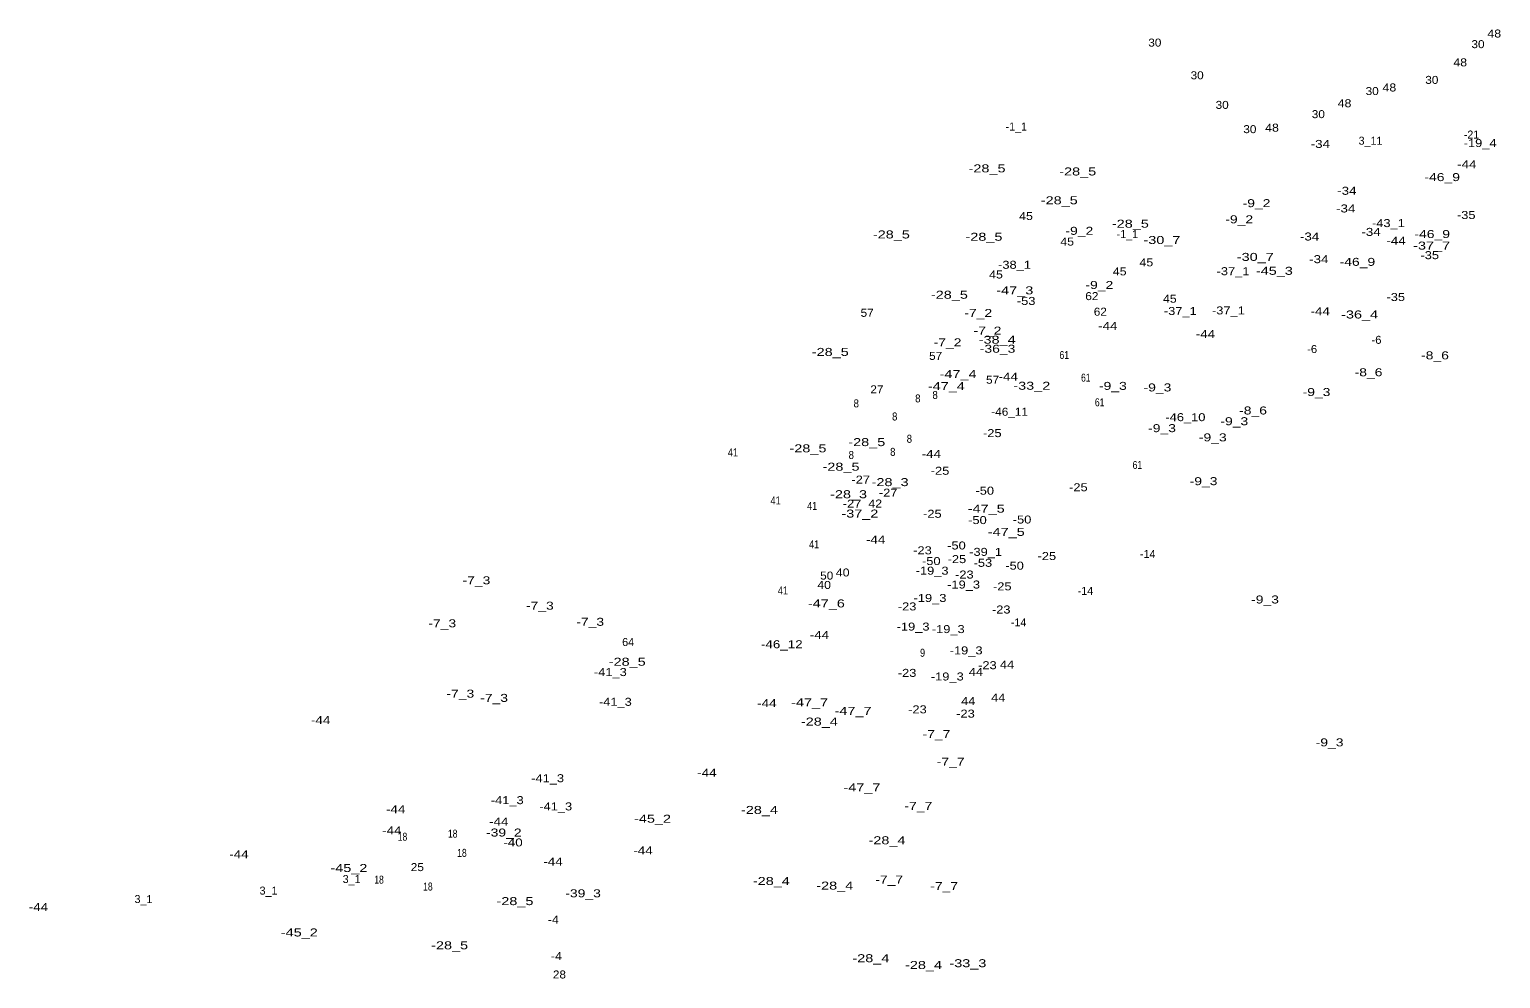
# Model space of a CAD drawing. Extents: x -663241 to -661169, y -1003538 to -1000899.
# Drawn here: x -662800 to -662065, y -1002217 to -1001743 of the extents above; entities that cross this region are included whole.
import ezdxf
from ezdxf.enums import TextEntityAlignment as Align

# ---------------------------------------------------------------- set-up
doc = ezdxf.new("R2010")
doc.units = 0
doc.header["$LTSCALE"] = 1.6
doc.layers.add('24', color=7, linetype='Continuous')

msp = doc.modelspace()

# ---------------------------------------------------------------- texts
at = {"layer": '24'}
for s, width, p in [('48', 1.15, (-662068.16, -1001746.79)), ('30', 1.1, (-662237.77, -1001751.33)), ('30', 1.1, (-662076.29, -1001752.1)), ('48', 1.15, (-662085.169, -1001761.22)), ('30', 1.1, (-662216.63, -1001767.67)), ('30', 1.1, (-662099.36, -1001769.98)), ('30', 1.1, (-662129.16, -1001775.56)), ('48', 1.15, (-662120.569, -1001773.77)), ('30', 1.1, (-662204.13, -1001782.48)), ('48', 1.15, (-662142.97, -1001781.65)), ('48', 1.15, (-662179.209, -1001793.86)), ('30', 1.1, (-662156.069, -1001787.1)), ('30', 1.1, (-662190.29, -1001794.6)), ('-34', 1.25, (-662155.06, -1001801.99)), ('-19_4', 1.2, (-662075.23, -1001801.55)), ('-28_5', 1.35, (-662321.61, -1001814.22)), ('-28_5', 1.35, (-662276.299, -1001815.76)), ('-44', 1.25, (-662081.86, -1001812.15)), ('-46_9', 1.3, (-662094.191, -1001818.58)), ('-28_5', 1.35, (-662285.52, -1001830.17)), ('-34', 1.25, (-662141.82, -1001825.42)), ('45', 1.15, (-662302.14, -1001838.04)), ('-9_2', 1.3, (-662186.97, -1001831.61)), ('-34', 1.25, (-662142.39, -1001834.26)), ('-35', 1.2, (-662082.16, -1001837.53)), ('-9_2', 1.3, (-662275.49, -1001845.44)), ('-28_5', 1.35, (-662250, -1001841.88)), ('-9_2', 1.3, (-662195.61, -1001839.68)), ('-43_1', 1.2, (-662121.059, -1001841.57)), ('-28_5', 1.35, (-662369.419, -1001847.25)), ('-28_5', 1.35, (-662323.15, -1001848.41)), ('45', 1.15, (-662281.569, -1001850.83)), ('-30_7', 1.35, (-662234.23, -1001850.03)), ('-34', 1.25, (-662160.44, -1001848.28)), ('-34', 1.25, (-662129.72, -1001845.97)), ('-44', 1.25, (-662117.23, -1001850.42)), ('-37_7', 1.35, (-662099.471, -1001852.83)), ('-46_9', 1.3, (-662099.181, -1001847.05)), ('-30_7', 1.35, (-662187.57, -1001858.48)), ('-34', 1.25, (-662155.83, -1001859.61)), ('-35', 1.2, (-662100.4, -1001857.61)), ('45', 1.15, (-662317.13, -1001867.27)), ('-38_1', 1.2, (-662307.88, -1001862.42)), ('45', 1.15, (-662255.329, -1001865.73)), ('45', 1.15, (-662242.01, -1001861.21)), ('-37_1', 1.2, (-662198.7, -1001865.62)), ('-45_3', 1.35, (-662178.05, -1001865.44)), ('-46_9', 1.3, (-662136.551, -1001860.96)), ('-9_2', 1.3, (-662265.5, -1001872.52)), ('-28_5', 1.35, (-662340.429, -1001877.4)), ('-47_3', 1.35, (-662307.74, -1001875.21)), ('-53', 1.2, (-662302.07, -1001880.5)), ('62', 1.1, (-662269.24, -1001878.09)), ('45', 1.15, (-662230.28, -1001879.38)), ('-35', 1.2, (-662117.39, -1001878.54)), ('57', 1.1, (-662381.52, -1001886.43)), ('-7_2', 1.3, (-662326.01, -1001886.5)), ('62', 1.1, (-662265.01, -1001885.88)), ('-37_1', 1.2, (-662225.04, -1001885.52)), ('-37_1', 1.2, (-662201.01, -1001885.23)), ('-44', 1.25, (-662155.1, -1001885.62)), ('-36_4', 1.35, (-662135.45, -1001887.27)), ('-7_2', 1.3, (-662321.4, -1001895.34)), ('-44', 1.25, (-662261.29, -1001893)), ('-7_2', 1.3, (-662341.37, -1001901.2)), ('-38_4', 1.35, (-662316.55, -1001899.89)), ('-44', 1.25, (-662212.47, -1001897.04)), ('-6', 1.05, (-662127.02, -1001899.94)), ('-28_5', 1.35, (-662399.949, -1001905.99)), ('57', 1.1, (-662347.3, -1001907.97)), ('-36_3', 1.3, (-662316.35, -1001904.4)), ('61', 0.8, (-662283.03, -1001907.52)), ('-6', 1.05, (-662159.18, -1001904.55)), ('-8_6', 1.3, (-662097.78, -1001907.71)), ('-47_4', 1.35, (-662336.09, -1001917.05)), ('-44', 1.25, (-662311.01, -1001918.34)), ('61', 0.8, (-662272.26, -1001918.86)), ('-8_6', 1.3, (-662131, -1001916.16)), ('27', 1.1, (-662376.65, -1001924.7)), ('-47_4', 1.35, (-662341.949, -1001923.11)), ('57', 1.1, (-662318.85, -1001919.9)), ('-33_2', 1.35, (-662299.25, -1001922.91)), ('-9_3', 1.3, (-662258.75, -1001922.97)), ('-9_3', 1.3, (-662236.47, -1001923.74)), ('-9_3', 1.3, (-662156.98, -1001926.05)), ('8', 0.9, (-662386.959, -1001931.73)), ('8', 0.9, (-662356.199, -1001929.23)), ('8', 0.9, (-662347.559, -1001927.51)), ('61', 0.8, (-662265.341, -1001931.17)), ('8', 0.9, (-662367.74, -1001938.27)), ('-46_11', 1.1, (-662310.33, -1001935.89)), ('-46_10', 1.2, (-662222.49, -1001938.62)), ('-9_3', 1.3, (-662198.07, -1001940.64)), ('-8_6', 1.3, (-662188.7, -1001935.27)), ('-25', 1.2, (-662318.99, -1001946.58)), ('-9_3', 1.3, (-662234.17, -1001944.1)), ('-28_5', 1.35, (-662411.09, -1001954.2)), ('-28_5', 1.35, (-662381.709, -1001951.09)), ('8', 0.9, (-662360.429, -1001949.42)), ('-9_3', 1.3, (-662208.82, -1001948.71)), ('41', 0.85, (-662448.6, -1001956.23)), ('8', 0.9, (-662389.459, -1001957.5)), ('8', 0.9, (-662368.699, -1001955.96)), ('-44', 1.25, (-662349.449, -1001956.99)), ('61', 0.8, (-662246.5, -1001962.52)), ('-28_5', 1.35, (-662394.579, -1001963.38)), ('-27', 1.2, (-662384.75, -1001969.84)), ('-25', 1.2, (-662345.1, -1001965.41)), ('-28_3', 1.35, (-662390.799, -1001977.14)), ('-28_3', 1.35, (-662370.059, -1001971.09)), ('-27', 1.2, (-662371.02, -1001976.37)), ('-50', 1.2, (-662322.76, -1001975.36)), ('-25', 1.2, (-662275.98, -1001973.66)), ('-9_3', 1.3, (-662213.43, -1001970.61)), ('41', 0.85, (-662427.26, -1001980.27)), ('41', 0.85, (-662409, -1001982.96)), ('-27', 1.2, (-662389.071, -1001981.84)), ('42', 1.15, (-662377.47, -1001981.8)), ('-47_5', 1.35, (-662322.02, -1001984.35)), ('-37_2', 1.35, (-662385.16, -1001986.81)), ('-25', 1.2, (-662348.94, -1001986.92)), ('-50', 1.2, (-662326.41, -1001990.07)), ('-50', 1.2, (-662304.11, -1001989.79)), ('-44', 1.25, (-662377.27, -1001999.78)), ('-47_5', 1.35, (-662312.02, -1001995.98)), ('41', 0.85, (-662408.03, -1002002.19)), ('-23', 1.2, (-662353.88, -1002005.2)), ('-50', 1.2, (-662336.89, -1002002.77)), ('-39_1', 1.2, (-662322.321, -1002005.96)), ('-50', 1.2, (-662349.48, -1002010.56)), ('-25', 1.2, (-662336.66, -1002009.58)), ('-53', 1.2, (-662323.69, -1002011.44)), ('-50', 1.2, (-662307.86, -1002012.86)), ('-25', 1.2, (-662291.73, -1002008.05)), ('-7_3', 1.3, (-662576.76, -1002020.18)), ('50', 1.1, (-662401.72, -1002017.82)), ('40', 1.15, (-662393.74, -1002016.26)), ('-19_3', 1.2, (-662349.071, -1002015.37)), ('-23', 1.2, (-662332.95, -1002017.3)), ('41', 0.85, (-662423.61, -1002025.27)), ('40', 1.15, (-662403.02, -1002022.5)), ('-19_3', 1.2, (-662350.12, -1002029.01)), ('-19_3', 1.2, (-662333.321, -1002022.29)), ('-25', 1.2, (-662314, -1002023.22)), ('-7_3', 1.3, (-662545.08, -1002032.87)), ('-47_6', 1.35, (-662401.91, -1002031.74)), ('-23', 1.2, (-662361.56, -1002033.24)), ('-23', 1.2, (-662314.52, -1002034.78)), ('-9_3', 1.3, (-662182.71, -1002029.77)), ('-7_3', 1.3, (-662593.85, -1002041.7)), ('-7_3', 1.3, (-662519.93, -1002040.94)), ('-19_3', 1.2, (-662358.571, -1002043.32)), ('-44', 1.25, (-662405.34, -1002047.48)), ('-19_3', 1.2, (-662341, -1002044.57)), ('-46_12', 1.25, (-662424.17, -1002052.15)), ('9', 0.85, (-662353.84, -1002056.41)), ('-19_3', 1.2, (-662332.071, -1002055.23)), ('-28_5', 1.35, (-662501.41, -1002060.9)), ('44', 1.2, (-662327.16, -1002065.95)), ('-23', 1.2, (-662321.43, -1002062.63)), ('44', 1.2, (-662311.59, -1002062.29)), ('-41_3', 1.2, (-662509.84, -1002066.06)), ('-23', 1.2, (-662361.56, -1002066.47)), ('-19_3', 1.2, (-662341.481, -1002068.27)), ('-7_3', 1.3, (-662584.82, -1002076.85)), ('-7_3', 1.3, (-662567.93, -1002078.97)), ('44', 1.2, (-662331.01, -1002080.56)), ('44', 1.2, (-662316.01, -1002078.83)), ('-41_3', 1.2, (-662507.34, -1002080.93)), ('-44', 1.25, (-662431.62, -1002081.6)), ('-47_7', 1.35, (-662410.27, -1002081.23)), ('-47_7', 1.35, (-662388.551, -1002085.46)), ('-23', 1.2, (-662356.39, -1002084.72)), ('-23', 1.2, (-662332.38, -1002086.83)), ('-44', 1.25, (-662654.61, -1002090.09)), ('-28_4', 1.35, (-662405.39, -1002090.81)), ('-7_7', 1.3, (-662346.9, -1002097.09)), ('-9_3', 1.3, (-662150.45, -1002101.22)), ('-44', 1.25, (-662461.6, -1002116.41)), ('-7_7', 1.3, (-662339.801, -1002110.92)), ('-41_3', 1.2, (-662541.179, -1002119.13)), ('-47_7', 1.35, (-662384.13, -1002123.73)), ('-41_3', 1.2, (-662561.36, -1002130.1)), ('-44', 1.25, (-662617.12, -1002134.67)), ('-41_3', 1.2, (-662537.14, -1002133.24)), ('-45_2', 1.35, (-662488.77, -1002139.39)), ('-28_4', 1.35, (-662435.34, -1002134.99)), ('-7_7', 1.3, (-662355.931, -1002133.01)), ('-44', 1.25, (-662619.04, -1002145.25)), ('18', 0.8, (-662588.62, -1002146.85)), ('-39_2', 1.3, (-662563.08, -1002146.3)), ('-44', 1.25, (-662565.6, -1002140.83)), ('18', 0.8, (-662613.699, -1002148.38)), ('-40', 1.25, (-662558.48, -1002151.24)), ('-28_4', 1.35, (-662371.6, -1002150.16)), ('-44', 1.25, (-662695.439, -1002157.18)), ('18', 0.8, (-662584, -1002156.46)), ('-44', 1.25, (-662538.5, -1002160.83)), ('-44', 1.25, (-662493.52, -1002155.26)), ('-45_2', 1.35, (-662640.48, -1002164.04)), ('25', 1.1, (-662606.299, -1002163.58)), ('18', 0.8, (-662625.429, -1002169.83)), ('18', 0.8, (-662601.01, -1002173.29)), ('-28_4', 1.35, (-662429.39, -1002170.52)), ('-28_4', 1.35, (-662397.71, -1002172.83)), ('-7_7', 1.3, (-662370.52, -1002169.81)), ('-7_7', 1.3, (-662343.061, -1002173.08)), ('-44', 1.25, (-662795.59, -1002183.52)), ('-28_5', 1.35, (-662557.5, -1002180.59)), ('-39_3', 1.3, (-662523.48, -1002176.68)), ('-4', 1.15, (-662538.34, -1002189.84)), ('-45_2', 1.35, (-662665.27, -1002196.26)), ('-28_5', 1.35, (-662590.14, -1002202.68)), ('-4', 1.15, (-662536.8, -1002208.08)), ('-28_4', 1.35, (-662379.66, -1002209.13)), ('-28_4', 1.35, (-662353.36, -1002212.52)), ('-33_3', 1.35, (-662331.179, -1002211.63)), ('28', 1.1, (-662535.29, -1002217.27))]:
    msp.add_text(s, height=4, dxfattribs=dict(at, width=width)).set_placement(p, align=Align.CENTER)
for s, p in [('-1_1', (-662306.99, -1001793.28)), ('3_11', (-662130, -1001800.38)), ('-21', (-662079.53, -1001797.3)), ('-1_1', (-662251.5, -1001847.07)), ('-14', (-662241.33, -1002007.02)), ('-14', (-662272.43, -1002025.46)), ('-14', (-662305.84, -1002041.21)), ('64', (-662500.957, -1002051.06)), ('3_1', (-662680.65, -1002175.32)), ('3_1', (-662639.13, -1002169.55)), ('3_1', (-662743.13, -1002179.55))]:
    msp.add_text(s, height=4, dxfattribs=at).set_placement(p, align=Align.CENTER)

doc.saveas('drawing.dxf')
